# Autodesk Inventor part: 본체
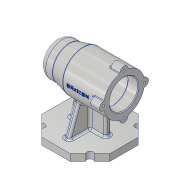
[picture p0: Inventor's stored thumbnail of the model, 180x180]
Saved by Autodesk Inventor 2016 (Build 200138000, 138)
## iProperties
Created: 2021-01
Part Number: 본체
Material: 알루미늄 6061
Document SubType Name: Modeling
Designer: MIRAE
Density: 2.7 g/cm^3
Appearance: 알루미늄 - 평지
Mass: 629.963 g
Surface Area: 613.774 cm^2
Volume: 233.32 cm^3
Author: MIRAE
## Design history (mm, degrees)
sketch "스케치1"
  geometry: L1 (-50, 0)-(50, 0); L2 (50, 30)-(-10, 30); L3 (-10, 30)-(-30, 25); L4 (-30, 25)-(-50, 25); L5 (-50, 25)-(-50, 0); L6 (-50, 0)-(-44, 0); L7 (-44, 0)-(-44, 10.5); L8 (-44, 10.5)-(-41, 10.5); L9 (-41, 10.5)-(-41, 16); L10 (-41, 16)-(-37, 16); L11 (-37, 16)-(-37, 17.5); L12 (-37, 17.5)-(-19, 17.5); L13 (-19, 17.5)-(-19, 21); L14 (-19, 21)-(-7, 21); L15 (35, 21)-(50, 21); L16 (50, 21)-(50, 30); L17 (-7, 24)-(35, 24); L18 (35, 24)-(35, 21); L19 (-7, 21)-(-7, 24); 1 further point
  constraints: 39 end point, 6 horizontal, 5 perpendicular, 3 vertical, 2 parallel, 1 midpoint, 1 vertical alignment
  dimensions: "d0" = 100 distance of L1.start L1.end; "d1" = 3 distance of L7.end L8.end; "d2" = 4 distance of L9.end L10.end; "d3" = 21 diameter of L8 L1; "d4" = 32 diameter of L10 L1; "d5" = 35 diameter of L12 L1; "d6" = 18 distance of L11.end L12.end; "d9" = 15 distance of L15.start L15.end; "d11" = 12 distance of L13.end L14.end; "d13" = 48 diameter of L17 L1; "d14" = 42 diameter of L15 L1; "d15" = 50 diameter of L4 L1; "d16" = 20 distance from line of L3.end L5; "d17" = 40 distance from line of L2.end L5; "d18" = 60 diameter of L2 L1; "d19" = 50 distance of point (0, 0) L1.start; "d20" = 42 diameter of L14 L1; "d22" = 42 distance of L17.start L17.end
revolve "회전1" sketch "스케치1" stored, may be unused: angle "d23" = 90 deg
fillet "모깎기1" dims "d24" = 10
node "작업 평면1"
sketch "스케치2"
  geometry: L1 (-50, -20.711)-(-50, 20.711); L2 (-50, 20.711)-(-20.711, 50); L3 (-20.711, 50)-(20.711, 50); L4 (20.711, 50)-(50, 20.711); L5 (50, 20.711)-(50, -20.711); L6 (50, -20.711)-(20.711, -50); L7 (20.711, -50)-(-20.711, -50); L8 (-20.711, -50)-(-50, -20.711); 2 further points
  constraints: 16 end point, 1 coincident, 1 horizontal, 17 other
  dimensions: "d26" = 50 distance from line of L1 point (0, 0)
extrude "돌출1" join sketch "스케치2" distance "d27" = 10; taper "d28" = 0 deg
sketch "스케치3"
  geometry: L1 (50, 20.711)-(50, -20.711) reference; L2 (50, -20.711)-(20.711, -50) reference; L3 (20.711, -50)-(-20.711, -50) reference; L4 (-20.711, -50)-(-50, -20.711) reference; L5 (-50, -20.711)-(-50, 20.711) reference; L6 (-50, 20.711)-(-20.711, 50) reference; L7 (-20.711, 50)-(20.711, 50) reference; L8 (20.711, 50)-(50, 20.711) reference; 9 further points
  constraints: 4 coincident, 4 midpoint
hole "구멍1" sketch "스케치3" at (-35.355, 35.355), (35.355, 35.355), (-35.355, -35.355), (35.355, -35.355) diameter "d29" = 9; stored, may be unused: countersink angle "d33" = 90 deg, drill point angle "d35" = 118 deg; dims "d30" = 6, "d31" = 4, "d32" = 2, "d34" = 8
sketch "스케치4"
  geometry: L1 (20.711, -65)-(-20.711, -65) reference; L2 (0, -65)-(0, -25.738); L3 (27, -25.738)-(27, -65); L4 (50, -75)-(50, -65) reference; L5 (32.173, -65)-(20.711, -65) reference; L6 (27, -65)-(0, -65); L7 (27, -25.738)-(0, -25.738); 1 further point
  constraints: 8 end point, 1 collinear, 1 horizontal, 1 midpoint, 1 point on line, 1 vertical
  dimensions: "d36" = 23 distance between parallel lines of L4 L3; "d62" = 39.26208 distance of L2.start L2.end
extrude "돌출2" join sketch "스케치4" stored distance "d37" = 8; taper "d38" = 0 deg
sketch "스케치7"
  geometry: C1 r 21 at (0, 0) reference; C2 r 6 at (0, 30); 2 further points
  constraints: 2 vertical alignment, 1 centre point, 1 other
  dimensions: "d43" = 6 radius of C2
extrude "돌출3" join sketch "스케치7" distance "d44" = 16; taper "d45" = 0 deg
hole "구멍2" diameter "d48" = 3.242; stored, may be unused: countersink angle "d52" = 90 deg, drill point angle "d54" = 120 deg; dims "d46" = 10, "d47" = 10, "d49" = 8, "d50" = 4, "d51" = 2, "d53" = 10
sketch "스케치8"
  geometry: L1 (0, -25.515)-(-27, -25.515); L2 (-27, -25.515)-(-27, -65); L3 (-27, -65)-(0, -65); L4 (0, -65)-(0, -25.515); L5 (-50, -75)-(-50, -65) reference; 2 further points
  constraints: 8 end point, 2 parallel, 1 horizontal, 1 horizontal alignment, 1 perpendicular, 1 vertical alignment
  dimensions: "d58" = 23 distance between parallel lines of L2 L5
extrude "돌출4" new body sketch "스케치8" stored distance "d59" = 8; taper "d60" = 0 deg
node "작업 평면2"
feature "면 기울기1" dims angle "d61" = 11 deg
feature "결합1"
  node "솔리드2"
sketch "스케치10"
  geometry: L1 (-65, 35)-(-65, 0); L2 (-65, 0)-(-29.732, 0); L3 (-17.104, 17.567)-(-65, 35); L4 (-65, 38.537)-(-65, 50) reference; L5 (-75, 50)-(-65, 50) reference; L6 (-29.732, 0)-(-17.104, 17.567); 2 further points
  constraints: 8 end point, 2 vertical alignment, 1 horizontal, 1 horizontal alignment, 1 vertical
  dimensions: "d66" = 110 deg angle of L3 L4; "d84" = 15 distance from line of L1.start L5
extrude "돌출5" join sketch "스케치10" stored distance "d69" = 8; taper "d70" = 0 deg
fillet "모깎기2" dims "d71" = 3
fillet "모깎기3" dims "d72" = 1
chamfer "모따기1" distance "d73" = 1; stored, may be unused: second distance "d74" = 2, angle "d75" = 45 deg
fillet "모깎기4" dims "d76" = 3
fillet "모깎기5" dims "d77" = 0.3
fillet "모깎기6" dims "d78" = 3
fillet "모깎기7" dims "d79" = 3
fillet "모깎기8" dims "d80" = 3
node "작업 평면3"
sketch "스케치11"
  geometry: L1 (30, 6.771)-(30, 29.226) reference; 2 further points
  constraints: 1 horizontal alignment, 1 other
  dimensions: "d81" = 38 distance from line of point (-8, 0) L1
feature "엠보싱1" sketch "스케치11" dims "d0" = 100, "d1" = 3, "d2" = 4, "d3" = 21, "d4" = 32, "d5" = 35, "d6" = 18, "d9" = 15, "d11" = 12, "d13" = 48, "d14" = 42, "d15" = 50, "d16" = 20, "d17" = 40, "d18" = 60, "d19" = 50, "d20" = 42, "d22" = 42, "d82" = 0.5, "d83" = 0
node "솔리드1"
pattern_circular "원형 패턴1" dims angle "d56" = 360 deg
mirror "대칭1"
node "투영된 루프1"
node "투영된 루프7"
other parameters: "d25" = -75
